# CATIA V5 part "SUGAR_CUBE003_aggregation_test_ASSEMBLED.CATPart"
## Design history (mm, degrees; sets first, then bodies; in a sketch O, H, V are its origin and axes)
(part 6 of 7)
Body52 "sugar_cube003_Aa006"
  Line326: type PtDir, RefPoint vertex of Line4, Direction edge [XY plane of AxisSystem1 | ZX plane of AxisSystem1], Start 0, End 4876.8 {= Body52.X1}
  Line327: type PtDir, RefPoint vertex of Line4, Direction edge [XY plane of AxisSystem1 | ZX plane of AxisSystem1], Start 0, End 4876.8 {= Body52.X2}
  Line328: type PtDir, RefPoint vertex of Line4, Direction edge [YZ plane of AxisSystem1 | XY plane of AxisSystem1], Start 0, End 3657.6 {= Body52.Y1}
  Line329: type PtDir, RefPoint vertex of Line4, Direction edge [YZ plane of AxisSystem1 | XY plane of AxisSystem1], Start 0, End 3352.8 {= Body52.Y2}
  Line330: type PtDir, RefPoint vertex of Line4, Direction edge [ZX plane of AxisSystem1 | YZ plane of AxisSystem1], Start 0, End 3048 {= Body52.Z1}
  Line331: type PtDir, RefPoint vertex of Line4, Direction edge [ZX plane of AxisSystem1 | YZ plane of AxisSystem1], Start 0, End 4572 {= Body52.Z2}
  Plane661: type Normal, Curve Line326, RefPoint vertex of Line326
  Plane662: type Normal, Curve Line327, RefPoint vertex of Line327
  Plane663: type Normal, Curve Line328, RefPoint vertex of Line328
  Plane664: type Normal, Curve Line329, RefPoint vertex of Line329
  Plane665: type Normal, Curve Line330, RefPoint vertex of Line330
  Plane666: type Normal, Curve Line331, RefPoint vertex of Line331
  Plane667: type 3Points, Element1 vertex of Line4, Element2 vertex of Line328, Element3 vertex of Line326
  Intersect1001: ToIntersect1 Plane663, ToIntersect2 Plane662
  Intersect1002: ToIntersect1 Plane661, ToIntersect2 Plane663
  Intersect1003: ToIntersect1 Plane661, ToIntersect2 Plane664
  Intersect1004: ToIntersect1 Plane664, ToIntersect2 Plane662
  MultiSel51
  LineCorner51: Elements ({intersect ToIntersect1 Plane667, ToIntersect2 Intersect1003}; {intersect ToIntersect1 Plane667, ToIntersect2 Intersect1004}; {intersect ToIntersect1 Plane667, ToIntersect2 Intersect1001}; {intersect ToIntersect1 Plane667, ToIntersect2 Intersect1002})
  Pad202: profile LineCorner51, up to Plane665, opposite side up to Plane666
  Plane668: type Offset, RefPlane Plane664, Offset 609.6 {= thickness}
  Plane669: type Offset, RefPlane Plane663, Offset 609.6 {= thickness}, reversed
  Plane670: type Offset, RefPlane Plane661, Offset 609.6 {= thickness}, reversed
  Plane671: type Offset, RefPlane Plane662, Offset 609.6 {= thickness}
  Plane672: type Offset, RefPlane Plane666, Offset 609.6 {= thickness}
  Plane673: type Offset, RefPlane Plane665, Offset 609.6 {= thickness}, reversed
  Intersect1005: ToIntersect1 Plane668, ToIntersect2 Plane661
  Intersect1006: ToIntersect1 Plane669, ToIntersect2 Plane661
  Intersect1007: ToIntersect1 Plane672, ToIntersect2 Plane661
  Intersect1008: ToIntersect1 Plane673, ToIntersect2 Plane661
  Trim601: Trimmed (Intersect1005; Intersect1008)
  Trim602: Trimmed (Trim601; Intersect1006)
  Trim603: Trimmed (Trim602; Intersect1007)
  Pocket206: profile Trim603, up to Plane671, deactivated
  Pad203: profile LineCorner51, up to Plane665, opposite side up to Plane666, deactivated
  Intersect1009: ToIntersect1 Plane669, ToIntersect2 Plane662
  Intersect1010: ToIntersect1 Plane662, ToIntersect2 Plane668
  Intersect1011: ToIntersect1 Plane672, ToIntersect2 Plane662
  Intersect1012: ToIntersect1 Plane673, ToIntersect2 Plane662
  Trim604: Trimmed (Intersect1012; Intersect1009)
  Trim605: Trimmed (Trim604; Intersect1011)
  Trim606: Trimmed (Trim605; Intersect1010)
  Pocket207: profile Trim606, up to Plane670, deactivated
  Intersect1013: ToIntersect1 Plane671, ToIntersect2 Plane664
  Intersect1014: ToIntersect1 Plane672, ToIntersect2 Plane664
  Intersect1015: ToIntersect1 Plane664, ToIntersect2 Plane670
  Intersect1016: ToIntersect1 Plane673, ToIntersect2 Plane664
  Trim607: Trimmed (Intersect1013; Intersect1016)
  Trim608: Trimmed (Trim607; Intersect1015)
  Trim609: Trimmed (Trim608; Intersect1014)
  Pad204: profile LineCorner51, up to Plane665, opposite side up to Plane666
  Pocket208: profile Trim609, up to Plane669
  Intersect1017: ToIntersect1 Plane670, ToIntersect2 Plane663
  Intersect1018: ToIntersect1 Plane672, ToIntersect2 Plane663
  Intersect1019: ToIntersect1 Plane671, ToIntersect2 Plane663
  Intersect1020: ToIntersect1 Plane673, ToIntersect2 Plane663
  Trim610: Trimmed (Intersect1017; Intersect1020)
  Trim611: Trimmed (Trim610; Intersect1019)
  Trim612: Trimmed (Trim611; Intersect1018)
  Pad205: profile LineCorner51, up to Plane665, opposite side up to Plane666, deactivated
  Pocket209: profile Trim612, up to Plane668, deactivated
Body53 "sugar_cube003_Ab006"
  Line332: type PtDir, RefPoint vertex of Line3, Direction edge [XY plane of AxisSystem1 | ZX plane of AxisSystem1], Start 0, End 3962.4 {= Body53.X1}
  Line333: type PtDir, RefPoint vertex of Line3, Direction edge [XY plane of AxisSystem1 | ZX plane of AxisSystem1], Start 0, End 3657.6 {= Body53.X2}
  Line334: type PtDir, RefPoint vertex of Line3, Direction edge [YZ plane of AxisSystem1 | XY plane of AxisSystem1], Start 0, End 4876.8 {= Body53.Y1}
  Line335: type PtDir, RefPoint vertex of Line3, Direction edge [YZ plane of AxisSystem1 | XY plane of AxisSystem1], Start 0, End 3962.4 {= Body53.Y2}
  Line336: type PtDir, RefPoint vertex of Line3, Direction edge [ZX plane of AxisSystem1 | YZ plane of AxisSystem1], Start 0, End 3352.8 {= Body53.Z1}
  Line337: type PtDir, RefPoint vertex of Line3, Direction edge [ZX plane of AxisSystem1 | YZ plane of AxisSystem1], Start 0, End 3657.6 {= Body53.Z2}
  Plane674: type Normal, Curve Line332, RefPoint vertex of Line332
  Plane675: type Normal, Curve Line333, RefPoint vertex of Line333
  Plane676: type Normal, Curve Line334, RefPoint vertex of Line334
  Plane677: type Normal, Curve Line335, RefPoint vertex of Line335
  Plane678: type Normal, Curve Line336, RefPoint vertex of Line336
  Plane679: type Normal, Curve Line337, RefPoint vertex of Line337
  Plane680: type 3Points, Element1 vertex of Line3, Element2 vertex of Line334, Element3 vertex of Line332
  Intersect1021: ToIntersect1 Plane676, ToIntersect2 Plane675
  Intersect1022: ToIntersect1 Plane674, ToIntersect2 Plane676
  Intersect1023: ToIntersect1 Plane674, ToIntersect2 Plane677
  Intersect1024: ToIntersect1 Plane677, ToIntersect2 Plane675
  MultiSel52
  LineCorner52: Elements ({intersect ToIntersect1 Plane680, ToIntersect2 Intersect1023}; {intersect ToIntersect1 Plane680, ToIntersect2 Intersect1024}; {intersect ToIntersect1 Plane680, ToIntersect2 Intersect1021}; {intersect ToIntersect1 Plane680, ToIntersect2 Intersect1022})
  Pad206: profile LineCorner52, up to Plane678, opposite side up to Plane679
  Plane681: type Offset, RefPlane Plane677, Offset 609.6 {= thickness}
  Plane682: type Offset, RefPlane Plane676, Offset 609.6 {= thickness}, reversed
  Plane683: type Offset, RefPlane Plane674, Offset 609.6 {= thickness}, reversed
  Plane684: type Offset, RefPlane Plane675, Offset 609.6 {= thickness}
  Plane685: type Offset, RefPlane Plane679, Offset 609.6 {= thickness}
  Plane686: type Offset, RefPlane Plane678, Offset 609.6 {= thickness}, reversed
  Intersect1025: ToIntersect1 Plane681, ToIntersect2 Plane674
  Intersect1026: ToIntersect1 Plane682, ToIntersect2 Plane674
  Intersect1027: ToIntersect1 Plane685, ToIntersect2 Plane674
  Intersect1028: ToIntersect1 Plane686, ToIntersect2 Plane674
  Trim613: Trimmed (Intersect1025; Intersect1028)
  Trim614: Trimmed (Trim613; Intersect1026)
  Trim615: Trimmed (Trim614; Intersect1027)
  Pocket210: profile Trim615, up to Plane684
  Pad207: profile LineCorner52, up to Plane678, opposite side up to Plane679, deactivated
  Intersect1029: ToIntersect1 Plane682, ToIntersect2 Plane675
  Intersect1030: ToIntersect1 Plane675, ToIntersect2 Plane681
  Intersect1031: ToIntersect1 Plane685, ToIntersect2 Plane675
  Intersect1032: ToIntersect1 Plane686, ToIntersect2 Plane675
  Trim616: Trimmed (Intersect1032; Intersect1029)
  Trim617: Trimmed (Trim616; Intersect1031)
  Trim618: Trimmed (Trim617; Intersect1030)
  Pocket211: profile Trim618, up to Plane683, deactivated
  Intersect1033: ToIntersect1 Plane684, ToIntersect2 Plane677
  Intersect1034: ToIntersect1 Plane685, ToIntersect2 Plane677
  Intersect1035: ToIntersect1 Plane677, ToIntersect2 Plane683
  Intersect1036: ToIntersect1 Plane686, ToIntersect2 Plane677
  Trim619: Trimmed (Intersect1033; Intersect1036)
  Trim620: Trimmed (Trim619; Intersect1035)
  Trim621: Trimmed (Trim620; Intersect1034)
  Pad208: profile LineCorner52, up to Plane678, opposite side up to Plane679, deactivated
  Pocket212: profile Trim621, up to Plane682, deactivated
  Intersect1037: ToIntersect1 Plane683, ToIntersect2 Plane676
  Intersect1038: ToIntersect1 Plane685, ToIntersect2 Plane676
  Intersect1039: ToIntersect1 Plane684, ToIntersect2 Plane676
  Intersect1040: ToIntersect1 Plane686, ToIntersect2 Plane676
  Trim622: Trimmed (Intersect1037; Intersect1040)
  Trim623: Trimmed (Trim622; Intersect1039)
  Trim624: Trimmed (Trim623; Intersect1038)
  Pad209: profile LineCorner52, up to Plane678, opposite side up to Plane679, deactivated
  Pocket213: profile Trim624, up to Plane681, deactivated
Body54 "sugar_cube003Ac006"
  Line338: type PtDir, RefPoint vertex of Line2, Direction edge [XY plane of AxisSystem1 | ZX plane of AxisSystem1], Start 0, End 4572 {= Body54.X1}
  Line339: type PtDir, RefPoint vertex of Line2, Direction edge [XY plane of AxisSystem1 | ZX plane of AxisSystem1], Start 0, End 5791.2 {= Body54.X2}
  Line340: type PtDir, RefPoint vertex of Line2, Direction edge [YZ plane of AxisSystem1 | XY plane of AxisSystem1], Start 0, End 3048 {= Body54.Y1}
  Line341: type PtDir, RefPoint vertex of Line2, Direction edge [YZ plane of AxisSystem1 | XY plane of AxisSystem1], Start 0, End 3657.6 {= Body54.Y2}
  Line342: type PtDir, RefPoint vertex of Line2, Direction edge [ZX plane of AxisSystem1 | YZ plane of AxisSystem1], Start 0, End 6096 {= Body54.Z1}
  Line343: type PtDir, RefPoint vertex of Line2, Direction edge [ZX plane of AxisSystem1 | YZ plane of AxisSystem1], Start 0, End 4572 {= Body54.Z2}
  Plane687: type Normal, Curve Line338, RefPoint vertex of Line338
  Plane688: type Normal, Curve Line339, RefPoint vertex of Line339
  Plane689: type Normal, Curve Line340, RefPoint vertex of Line340
  Plane690: type Normal, Curve Line341, RefPoint vertex of Line341
  Plane691: type Normal, Curve Line342, RefPoint vertex of Line342
  Plane692: type Normal, Curve Line343, RefPoint vertex of Line343
  Plane693: type 3Points, Element1 vertex of Line2, Element2 vertex of Line340, Element3 vertex of Line338
  Intersect1041: ToIntersect1 Plane689, ToIntersect2 Plane688
  Intersect1042: ToIntersect1 Plane687, ToIntersect2 Plane689
  Intersect1043: ToIntersect1 Plane687, ToIntersect2 Plane690
  Intersect1044: ToIntersect1 Plane690, ToIntersect2 Plane688
  MultiSel53
  LineCorner53: Elements ({intersect ToIntersect1 Plane693, ToIntersect2 Intersect1043}; {intersect ToIntersect1 Plane693, ToIntersect2 Intersect1044}; {intersect ToIntersect1 Plane693, ToIntersect2 Intersect1041}; {intersect ToIntersect1 Plane693, ToIntersect2 Intersect1042})
  Pad210: profile LineCorner53, up to Plane691, opposite side up to Plane692, deactivated
  Plane694: type Offset, RefPlane Plane690, Offset 609.6 {= thickness}
  Plane695: type Offset, RefPlane Plane689, Offset 609.6 {= thickness}, reversed
  Plane696: type Offset, RefPlane Plane687, Offset 609.6 {= thickness}, reversed
  Plane697: type Offset, RefPlane Plane688, Offset 609.6 {= thickness}
  Plane698: type Offset, RefPlane Plane692, Offset 609.6 {= thickness}
  Plane699: type Offset, RefPlane Plane691, Offset 609.6 {= thickness}, reversed
  Intersect1045: ToIntersect1 Plane694, ToIntersect2 Plane687
  Intersect1046: ToIntersect1 Plane695, ToIntersect2 Plane687
  Intersect1047: ToIntersect1 Plane698, ToIntersect2 Plane687
  Intersect1048: ToIntersect1 Plane699, ToIntersect2 Plane687
  Trim625: Trimmed (Intersect1045; Intersect1048)
  Trim626: Trimmed (Trim625; Intersect1046)
  Trim627: Trimmed (Trim626; Intersect1047)
  Pocket214: profile Trim627, up to Plane697, deactivated
  Pad211: profile LineCorner53, up to Plane691, opposite side up to Plane692
  Intersect1049: ToIntersect1 Plane695, ToIntersect2 Plane688
  Intersect1050: ToIntersect1 Plane688, ToIntersect2 Plane694
  Intersect1051: ToIntersect1 Plane698, ToIntersect2 Plane688
  Intersect1052: ToIntersect1 Plane699, ToIntersect2 Plane688
  Trim628: Trimmed (Intersect1052; Intersect1049)
  Trim629: Trimmed (Trim628; Intersect1051)
  Trim630: Trimmed (Trim629; Intersect1050)
  Pocket215: profile Trim630, up to Plane696
  Intersect1053: ToIntersect1 Plane697, ToIntersect2 Plane690
  Intersect1054: ToIntersect1 Plane698, ToIntersect2 Plane690
  Intersect1055: ToIntersect1 Plane690, ToIntersect2 Plane696
  Intersect1056: ToIntersect1 Plane699, ToIntersect2 Plane690
  Trim631: Trimmed (Intersect1053; Intersect1056)
  Trim632: Trimmed (Trim631; Intersect1055)
  Trim633: Trimmed (Trim632; Intersect1054)
  Pad212: profile LineCorner53, up to Plane691, opposite side up to Plane692, deactivated
  Pocket216: profile Trim633, up to Plane695, deactivated
  Intersect1057: ToIntersect1 Plane696, ToIntersect2 Plane689
  Intersect1058: ToIntersect1 Plane698, ToIntersect2 Plane689
  Intersect1059: ToIntersect1 Plane697, ToIntersect2 Plane689
  Intersect1060: ToIntersect1 Plane699, ToIntersect2 Plane689
  Trim634: Trimmed (Intersect1057; Intersect1060)
  Trim635: Trimmed (Trim634; Intersect1059)
  Trim636: Trimmed (Trim635; Intersect1058)
  Pad213: profile LineCorner53, up to Plane691, opposite side up to Plane692, deactivated
  Pocket217: profile Trim636, up to Plane694, deactivated
Body55 "sugar_cube003_Ad006"
  Line344: type PtDir, RefPoint vertex of Line1, Direction edge [XY plane of AxisSystem1 | ZX plane of AxisSystem1], Start 0, End 4267.2 {= Body55.X1}
  Line345: type PtDir, RefPoint vertex of Line1, Direction edge [XY plane of AxisSystem1 | ZX plane of AxisSystem1], Start 0, End 6096 {= Body55.X2}
  Line346: type PtDir, RefPoint vertex of Line1, Direction edge [YZ plane of AxisSystem1 | XY plane of AxisSystem1], Start 0, End 3352.8 {= Body55.Y1}
  Line347: type PtDir, RefPoint vertex of Line1, Direction edge [YZ plane of AxisSystem1 | XY plane of AxisSystem1], Start 0, End 4267.2 {= Body55.Y2}
  Line348: type PtDir, RefPoint vertex of Line1, Direction edge [ZX plane of AxisSystem1 | YZ plane of AxisSystem1], Start 0, End 3962.4 {= Body55.Z1}
  Line349: type PtDir, RefPoint vertex of Line1, Direction edge [ZX plane of AxisSystem1 | YZ plane of AxisSystem1], Start 0, End 3962.4 {= Body55.Z2}
  Plane700: type Normal, Curve Line344, RefPoint vertex of Line344
  Plane701: type Normal, Curve Line345, RefPoint vertex of Line345
  Plane702: type Normal, Curve Line346, RefPoint vertex of Line346
  Plane703: type Normal, Curve Line347, RefPoint vertex of Line347
  Plane704: type Normal, Curve Line348, RefPoint vertex of Line348
  Plane705: type Normal, Curve Line349, RefPoint vertex of Line349
  Plane706: type 3Points, Element1 vertex of Line1, Element2 vertex of Line346, Element3 vertex of Line344
  Intersect1061: ToIntersect1 Plane702, ToIntersect2 Plane701
  Intersect1062: ToIntersect1 Plane700, ToIntersect2 Plane702
  Intersect1063: ToIntersect1 Plane700, ToIntersect2 Plane703
  Intersect1064: ToIntersect1 Plane703, ToIntersect2 Plane701
  MultiSel54
  LineCorner54: Elements ({intersect ToIntersect1 Plane706, ToIntersect2 Intersect1063}; {intersect ToIntersect1 Plane706, ToIntersect2 Intersect1064}; {intersect ToIntersect1 Plane706, ToIntersect2 Intersect1061}; {intersect ToIntersect1 Plane706, ToIntersect2 Intersect1062})
  Pad214: profile LineCorner54, up to Plane704, opposite side up to Plane705, deactivated
  Plane707: type Offset, RefPlane Plane703, Offset 609.6 {= thickness}
  Plane708: type Offset, RefPlane Plane702, Offset 609.6 {= thickness}, reversed
  Plane709: type Offset, RefPlane Plane700, Offset 609.6 {= thickness}, reversed
  Plane710: type Offset, RefPlane Plane701, Offset 609.6 {= thickness}
  Plane711: type Offset, RefPlane Plane705, Offset 609.6 {= thickness}
  Plane712: type Offset, RefPlane Plane704, Offset 609.6 {= thickness}, reversed
  Intersect1065: ToIntersect1 Plane707, ToIntersect2 Plane700
  Intersect1066: ToIntersect1 Plane708, ToIntersect2 Plane700
  Intersect1067: ToIntersect1 Plane711, ToIntersect2 Plane700
  Intersect1068: ToIntersect1 Plane712, ToIntersect2 Plane700
  Trim637: Trimmed (Intersect1065; Intersect1068)
  Trim638: Trimmed (Trim637; Intersect1066)
  Trim639: Trimmed (Trim638; Intersect1067)
  Pocket218: profile Trim639, up to Plane710, deactivated
  Pad215: profile LineCorner54, up to Plane704, opposite side up to Plane705
  Intersect1069: ToIntersect1 Plane708, ToIntersect2 Plane701
  Intersect1070: ToIntersect1 Plane701, ToIntersect2 Plane707
  Intersect1071: ToIntersect1 Plane711, ToIntersect2 Plane701
  Intersect1072: ToIntersect1 Plane712, ToIntersect2 Plane701
  Trim640: Trimmed (Intersect1072; Intersect1069)
  Trim641: Trimmed (Trim640; Intersect1071)
  Trim642: Trimmed (Trim641; Intersect1070)
  Pocket219: profile Trim642, up to Plane709
  Intersect1073: ToIntersect1 Plane710, ToIntersect2 Plane703
  Intersect1074: ToIntersect1 Plane711, ToIntersect2 Plane703
  Intersect1075: ToIntersect1 Plane703, ToIntersect2 Plane709
  Intersect1076: ToIntersect1 Plane712, ToIntersect2 Plane703
  Trim643: Trimmed (Intersect1073; Intersect1076)
  Trim644: Trimmed (Trim643; Intersect1075)
  Trim645: Trimmed (Trim644; Intersect1074)
  Pad216: profile LineCorner54, up to Plane704, opposite side up to Plane705, deactivated
  Pocket220: profile Trim645, up to Plane708, deactivated
  Intersect1077: ToIntersect1 Plane709, ToIntersect2 Plane702
  Intersect1078: ToIntersect1 Plane711, ToIntersect2 Plane702
  Intersect1079: ToIntersect1 Plane710, ToIntersect2 Plane702
  Intersect1080: ToIntersect1 Plane712, ToIntersect2 Plane702
  Trim646: Trimmed (Intersect1077; Intersect1080)
  Trim647: Trimmed (Trim646; Intersect1079)
  Trim648: Trimmed (Trim647; Intersect1078)
  Pad217: profile LineCorner54, up to Plane704, opposite side up to Plane705, deactivated
  Pocket221: profile Trim648, up to Plane707, deactivated
Body56 "_Ae006"
  Line350: type PtDir, RefPoint vertex of Line25, Direction edge [XY plane of AxisSystem1 | ZX plane of AxisSystem1], Start 0, End 4572 {= Body56.X1}
  Line351: type PtDir, RefPoint vertex of Line25, Direction edge [XY plane of AxisSystem1 | ZX plane of AxisSystem1], Start 0, End 5486.4 {= Body56.X2}
  Line352: type PtDir, RefPoint vertex of Line25, Direction edge [YZ plane of AxisSystem1 | XY plane of AxisSystem1], Start 0, End 3048 {= Body56.Y1}
  Line353: type PtDir, RefPoint vertex of Line25, Direction edge [YZ plane of AxisSystem1 | XY plane of AxisSystem1], Start 0, End 4267.2 {= Body56.Y2}
  Line354: type PtDir, RefPoint vertex of Line25, Direction edge [ZX plane of AxisSystem1 | YZ plane of AxisSystem1], Start 0, End 5791.2 {= Body56.Z1}
  Line355: type PtDir, RefPoint vertex of Line25, Direction edge [ZX plane of AxisSystem1 | YZ plane of AxisSystem1], Start 0, End 3048 {= Body56.Z2}
  Plane713: type Normal, Curve Line350, RefPoint vertex of Line350
  Plane714: type Normal, Curve Line351, RefPoint vertex of Line351
  Plane715: type Normal, Curve Line352, RefPoint vertex of Line352
  Plane716: type Normal, Curve Line353, RefPoint vertex of Line353
  Plane717: type Normal, Curve Line354, RefPoint vertex of Line354
  Plane718: type Normal, Curve Line355, RefPoint vertex of Line355
  Plane719: type 3Points, Element1 vertex of Line25, Element2 vertex of Line352, Element3 vertex of Line350
  Intersect1081: ToIntersect1 Plane715, ToIntersect2 Plane714
  Intersect1082: ToIntersect1 Plane713, ToIntersect2 Plane715
  Intersect1083: ToIntersect1 Plane713, ToIntersect2 Plane716
  Intersect1084: ToIntersect1 Plane716, ToIntersect2 Plane714
  MultiSel55
  LineCorner55: Elements ({intersect ToIntersect1 Plane719, ToIntersect2 Intersect1083}; {intersect ToIntersect1 Plane719, ToIntersect2 Intersect1084}; {intersect ToIntersect1 Plane719, ToIntersect2 Intersect1081}; {intersect ToIntersect1 Plane719, ToIntersect2 Intersect1082})
  Pad218: profile LineCorner55, up to Plane717, opposite side up to Plane718, deactivated
  Plane720: type Offset, RefPlane Plane716, Offset 609.6 {= thickness}
  Plane721: type Offset, RefPlane Plane715, Offset 609.6 {= thickness}, reversed
  Plane722: type Offset, RefPlane Plane713, Offset 609.6 {= thickness}, reversed
  Plane723: type Offset, RefPlane Plane714, Offset 609.6 {= thickness}
  Plane724: type Offset, RefPlane Plane718, Offset 609.6 {= thickness}
  Plane725: type Offset, RefPlane Plane717, Offset 609.6 {= thickness}, reversed
  Intersect1085: ToIntersect1 Plane720, ToIntersect2 Plane713
  Intersect1086: ToIntersect1 Plane721, ToIntersect2 Plane713
  Intersect1087: ToIntersect1 Plane724, ToIntersect2 Plane713
  Intersect1088: ToIntersect1 Plane725, ToIntersect2 Plane713
  Trim649: Trimmed (Intersect1085; Intersect1088)
  Trim650: Trimmed (Trim649; Intersect1086)
  Trim651: Trimmed (Trim650; Intersect1087)
  Pocket222: profile Trim651, up to Plane723, deactivated
  Pad219: profile LineCorner55, up to Plane717, opposite side up to Plane718, deactivated
  Intersect1089: ToIntersect1 Plane721, ToIntersect2 Plane714
  Intersect1090: ToIntersect1 Plane714, ToIntersect2 Plane720
  Intersect1091: ToIntersect1 Plane724, ToIntersect2 Plane714
  Intersect1092: ToIntersect1 Plane725, ToIntersect2 Plane714
  Trim652: Trimmed (Intersect1092; Intersect1089)
  Trim653: Trimmed (Trim652; Intersect1091)
  Trim654: Trimmed (Trim653; Intersect1090)
  Pocket223: profile Trim654, up to Plane722, deactivated
  Intersect1093: ToIntersect1 Plane723, ToIntersect2 Plane716
  Intersect1094: ToIntersect1 Plane724, ToIntersect2 Plane716
  Intersect1095: ToIntersect1 Plane716, ToIntersect2 Plane722
  Intersect1096: ToIntersect1 Plane725, ToIntersect2 Plane716
  Trim655: Trimmed (Intersect1093; Intersect1096)
  Trim656: Trimmed (Trim655; Intersect1095)
  Trim657: Trimmed (Trim656; Intersect1094)
  Pad220: profile LineCorner55, up to Plane717, opposite side up to Plane718, deactivated
  Pocket224: profile Trim657, up to Plane721, deactivated
  Intersect1097: ToIntersect1 Plane722, ToIntersect2 Plane715
  Intersect1098: ToIntersect1 Plane724, ToIntersect2 Plane715
  Intersect1099: ToIntersect1 Plane723, ToIntersect2 Plane715
  Intersect1100: ToIntersect1 Plane725, ToIntersect2 Plane715
  Trim658: Trimmed (Intersect1097; Intersect1100)
  Trim659: Trimmed (Trim658; Intersect1099)
  Trim660: Trimmed (Trim659; Intersect1098)
  Pad221: profile LineCorner55, up to Plane717, opposite side up to Plane718, deactivated
  Pocket225: profile Trim660, up to Plane720, deactivated
Body57 "sugar_cube003Ba001"
  Line356: type PtDir, RefPoint vertex of Line9, Direction edge [XY plane of AxisSystem1 | ZX plane of AxisSystem1], Start 0, End 3657.6 {= Body57.X1}
  Line357: type PtDir, RefPoint vertex of Line9, Direction edge [XY plane of AxisSystem1 | ZX plane of AxisSystem1], Start 0, End 4876.8 {= Body57.X2}
  Line358: type PtDir, RefPoint vertex of Line9, Direction edge [YZ plane of AxisSystem1 | XY plane of AxisSystem1], Start 0, End 4267.2 {= Body57.Y1}
  Line359: type PtDir, RefPoint vertex of Line9, Direction edge [YZ plane of AxisSystem1 | XY plane of AxisSystem1], Start 0, End 5181.6 {= Body57.Y2}
  Line360: type PtDir, RefPoint vertex of Line9, Direction edge [ZX plane of AxisSystem1 | YZ plane of AxisSystem1], Start 0, End 5486.4 {= Body57.Z1}
  Line361: type PtDir, RefPoint vertex of Line9, Direction edge [ZX plane of AxisSystem1 | YZ plane of AxisSystem1], Start 0, End 3962.4 {= Body57.Z2}
  Plane726: type Normal, Curve Line356, RefPoint vertex of Line356
  Plane727: type Normal, Curve Line357, RefPoint vertex of Line357
  Plane728: type Normal, Curve Line358, RefPoint vertex of Line358
  Plane729: type Normal, Curve Line359, RefPoint vertex of Line359
  Plane730: type Normal, Curve Line360, RefPoint vertex of Line360
  Plane731: type Normal, Curve Line361, RefPoint vertex of Line361
  Plane732: type 3Points, Element1 vertex of Line9, Element2 vertex of Line358, Element3 vertex of Line356
  Intersect1101: ToIntersect1 Plane728, ToIntersect2 Plane727
  Intersect1102: ToIntersect1 Plane726, ToIntersect2 Plane728
  Intersect1103: ToIntersect1 Plane726, ToIntersect2 Plane729
  Intersect1104: ToIntersect1 Plane729, ToIntersect2 Plane727
  MultiSel56
  LineCorner56: Elements ({intersect ToIntersect1 Plane732, ToIntersect2 Intersect1103}; {intersect ToIntersect1 Plane732, ToIntersect2 Intersect1104}; {intersect ToIntersect1 Plane732, ToIntersect2 Intersect1101}; {intersect ToIntersect1 Plane732, ToIntersect2 Intersect1102})
  Pad222: profile LineCorner56, up to Plane730, opposite side up to Plane731
  Plane733: type Offset, RefPlane Plane729, Offset 609.6 {= thickness}
  Plane734: type Offset, RefPlane Plane728, Offset 609.6 {= thickness}, reversed
  Plane735: type Offset, RefPlane Plane726, Offset 609.6 {= thickness}, reversed
  Plane736: type Offset, RefPlane Plane727, Offset 609.6 {= thickness}
  Plane737: type Offset, RefPlane Plane731, Offset 609.6 {= thickness}
  Plane738: type Offset, RefPlane Plane730, Offset 609.6 {= thickness}, reversed
  Intersect1105: ToIntersect1 Plane733, ToIntersect2 Plane726
  Intersect1106: ToIntersect1 Plane734, ToIntersect2 Plane726
  Intersect1107: ToIntersect1 Plane737, ToIntersect2 Plane726
  Intersect1108: ToIntersect1 Plane738, ToIntersect2 Plane726
  Trim661: Trimmed (Intersect1105; Intersect1108)
  Trim662: Trimmed (Trim661; Intersect1106)
  Trim663: Trimmed (Trim662; Intersect1107)
  Pocket226: profile Trim663, up to Plane736, deactivated
  Pad223: profile LineCorner56, up to Plane730, opposite side up to Plane731, deactivated
  Intersect1109: ToIntersect1 Plane734, ToIntersect2 Plane727
  Intersect1110: ToIntersect1 Plane727, ToIntersect2 Plane733
  Intersect1111: ToIntersect1 Plane737, ToIntersect2 Plane727
  Intersect1112: ToIntersect1 Plane738, ToIntersect2 Plane727
  Trim664: Trimmed (Intersect1112; Intersect1109)
  Trim665: Trimmed (Trim664; Intersect1111)
  Trim666: Trimmed (Trim665; Intersect1110)
  Pocket227: profile Trim666, up to Plane735, deactivated
  Intersect1113: ToIntersect1 Plane736, ToIntersect2 Plane729
  Intersect1114: ToIntersect1 Plane737, ToIntersect2 Plane729
  Intersect1115: ToIntersect1 Plane729, ToIntersect2 Plane735
  Intersect1116: ToIntersect1 Plane738, ToIntersect2 Plane729
  Trim667: Trimmed (Intersect1113; Intersect1116)
  Trim668: Trimmed (Trim667; Intersect1115)
  Trim669: Trimmed (Trim668; Intersect1114)
  Pad224: profile LineCorner56, up to Plane730, opposite side up to Plane731, deactivated
  Pocket228: profile Trim669, up to Plane734, deactivated
  Intersect1117: ToIntersect1 Plane735, ToIntersect2 Plane728
  Intersect1118: ToIntersect1 Plane737, ToIntersect2 Plane728
  Intersect1119: ToIntersect1 Plane736, ToIntersect2 Plane728
  Intersect1120: ToIntersect1 Plane738, ToIntersect2 Plane728
  Trim670: Trimmed (Intersect1117; Intersect1120)
  Trim671: Trimmed (Trim670; Intersect1119)
  Trim672: Trimmed (Trim671; Intersect1118)
  Pad225: profile LineCorner56, up to Plane730, opposite side up to Plane731
  Pocket229: profile Trim672, up to Plane733
Body58 "sugar_cube003Bb001"
  Line362: type PtDir, RefPoint vertex of Line8, Direction edge [XY plane of AxisSystem1 | ZX plane of AxisSystem1], Start 0, End 4876.8 {= Body58.X1}
  Line363: type PtDir, RefPoint vertex of Line8, Direction edge [XY plane of AxisSystem1 | ZX plane of AxisSystem1], Start 0, End 6096 {= Body58.X2}
  Line364: type PtDir, RefPoint vertex of Line8, Direction edge [YZ plane of AxisSystem1 | XY plane of AxisSystem1], Start 0, End 3657.6 {= Body58.Y1}
  Line365: type PtDir, RefPoint vertex of Line8, Direction edge [YZ plane of AxisSystem1 | XY plane of AxisSystem1], Start 0, End 3962.4 {= Body58.Y2}
  Line366: type PtDir, RefPoint vertex of Line8, Direction edge [ZX plane of AxisSystem1 | YZ plane of AxisSystem1], Start 0, End 5791.2 {= Body58.Z1}
  Line367: type PtDir, RefPoint vertex of Line8, Direction edge [ZX plane of AxisSystem1 | YZ plane of AxisSystem1], Start 0, End 5181.6 {= Body58.Z2}
  Plane739: type Normal, Curve Line362, RefPoint vertex of Line362
  Plane740: type Normal, Curve Line363, RefPoint vertex of Line363
  Plane741: type Normal, Curve Line364, RefPoint vertex of Line364
  Plane742: type Normal, Curve Line365, RefPoint vertex of Line365
  Plane743: type Normal, Curve Line366, RefPoint vertex of Line366
  Plane744: type Normal, Curve Line367, RefPoint vertex of Line367
  Plane745: type 3Points, Element1 vertex of Line8, Element2 vertex of Line364, Element3 vertex of Line362
  Intersect1121: ToIntersect1 Plane741, ToIntersect2 Plane740
  Intersect1122: ToIntersect1 Plane739, ToIntersect2 Plane741
  Intersect1123: ToIntersect1 Plane739, ToIntersect2 Plane742
  Intersect1124: ToIntersect1 Plane742, ToIntersect2 Plane740
  MultiSel57
  LineCorner57: Elements ({intersect ToIntersect1 Plane745, ToIntersect2 Intersect1123}; {intersect ToIntersect1 Plane745, ToIntersect2 Intersect1124}; {intersect ToIntersect1 Plane745, ToIntersect2 Intersect1121}; {intersect ToIntersect1 Plane745, ToIntersect2 Intersect1122})
  Pad226: profile LineCorner57, up to Plane743, opposite side up to Plane744, deactivated
  Plane746: type Offset, RefPlane Plane742, Offset 609.6 {= thickness}
  Plane747: type Offset, RefPlane Plane741, Offset 609.6 {= thickness}, reversed
  Plane748: type Offset, RefPlane Plane739, Offset 609.6 {= thickness}, reversed
  Plane749: type Offset, RefPlane Plane740, Offset 609.6 {= thickness}
  Plane750: type Offset, RefPlane Plane744, Offset 609.6 {= thickness}
  Plane751: type Offset, RefPlane Plane743, Offset 609.6 {= thickness}, reversed
  Intersect1125: ToIntersect1 Plane746, ToIntersect2 Plane739
  Intersect1126: ToIntersect1 Plane747, ToIntersect2 Plane739
  Intersect1127: ToIntersect1 Plane750, ToIntersect2 Plane739
  Intersect1128: ToIntersect1 Plane751, ToIntersect2 Plane739
  Trim673: Trimmed (Intersect1125; Intersect1128)
  Trim674: Trimmed (Trim673; Intersect1126)
  Trim675: Trimmed (Trim674; Intersect1127)
  Pocket230: profile Trim675, up to Plane749, deactivated
  Pad227: profile LineCorner57, up to Plane743, opposite side up to Plane744, deactivated
  Intersect1129: ToIntersect1 Plane747, ToIntersect2 Plane740
  Intersect1130: ToIntersect1 Plane740, ToIntersect2 Plane746
  Intersect1131: ToIntersect1 Plane750, ToIntersect2 Plane740
  Intersect1132: ToIntersect1 Plane751, ToIntersect2 Plane740
  Trim676: Trimmed (Intersect1132; Intersect1129)
  Trim677: Trimmed (Trim676; Intersect1131)
  Trim678: Trimmed (Trim677; Intersect1130)
  Pocket231: profile Trim678, up to Plane748, deactivated
  Intersect1133: ToIntersect1 Plane749, ToIntersect2 Plane742
  Intersect1134: ToIntersect1 Plane750, ToIntersect2 Plane742
  Intersect1135: ToIntersect1 Plane742, ToIntersect2 Plane748
  Intersect1136: ToIntersect1 Plane751, ToIntersect2 Plane742
  Trim679: Trimmed (Intersect1133; Intersect1136)
  Trim680: Trimmed (Trim679; Intersect1135)
  Trim681: Trimmed (Trim680; Intersect1134)
  Pad228: profile LineCorner57, up to Plane743, opposite side up to Plane744
  Pocket232: profile Trim681, up to Plane747
  Intersect1137: ToIntersect1 Plane748, ToIntersect2 Plane741
  Intersect1138: ToIntersect1 Plane750, ToIntersect2 Plane741
  Intersect1139: ToIntersect1 Plane749, ToIntersect2 Plane741
  Intersect1140: ToIntersect1 Plane751, ToIntersect2 Plane741
  Trim682: Trimmed (Intersect1137; Intersect1140)
  Trim683: Trimmed (Trim682; Intersect1139)
  Trim684: Trimmed (Trim683; Intersect1138)
  Pad229: profile LineCorner57, up to Plane743, opposite side up to Plane744, deactivated
  Pocket233: profile Trim684, up to Plane746, deactivated
Body59 "sugar_cube003Bc001"
  Line368: type PtDir, RefPoint vertex of Line7, Direction edge [XY plane of AxisSystem1 | ZX plane of AxisSystem1], Start 0, End 4267.2 {= Body59.X1}
  Line369: type PtDir, RefPoint vertex of Line7, Direction edge [XY plane of AxisSystem1 | ZX plane of AxisSystem1], Start 0, End 4572 {= Body59.X2}
  Line370: type PtDir, RefPoint vertex of Line7, Direction edge [YZ plane of AxisSystem1 | XY plane of AxisSystem1], Start 0, End 3962.4 {= Body59.Y1}
  Line371: type PtDir, RefPoint vertex of Line7, Direction edge [YZ plane of AxisSystem1 | XY plane of AxisSystem1], Start 0, End 3352.8 {= Body59.Y2}
  Line372: type PtDir, RefPoint vertex of Line7, Direction edge [ZX plane of AxisSystem1 | YZ plane of AxisSystem1], Start 0, End 3962.4 {= Body59.Z1}
  Line373: type PtDir, RefPoint vertex of Line7, Direction edge [ZX plane of AxisSystem1 | YZ plane of AxisSystem1], Start 0, End 5486.4 {= Body59.Z2}
  Plane752: type Normal, Curve Line368, RefPoint vertex of Line368
  Plane753: type Normal, Curve Line369, RefPoint vertex of Line369
  Plane754: type Normal, Curve Line370, RefPoint vertex of Line370
  Plane755: type Normal, Curve Line371, RefPoint vertex of Line371
  Plane756: type Normal, Curve Line372, RefPoint vertex of Line372
  Plane757: type Normal, Curve Line373, RefPoint vertex of Line373
  Plane758: type 3Points, Element1 vertex of Line7, Element2 vertex of Line370, Element3 vertex of Line368
  Intersect1141: ToIntersect1 Plane754, ToIntersect2 Plane753
  Intersect1142: ToIntersect1 Plane752, ToIntersect2 Plane754
  Intersect1143: ToIntersect1 Plane752, ToIntersect2 Plane755
  Intersect1144: ToIntersect1 Plane755, ToIntersect2 Plane753
  MultiSel58
  LineCorner58: Elements ({intersect ToIntersect1 Plane758, ToIntersect2 Intersect1143}; {intersect ToIntersect1 Plane758, ToIntersect2 Intersect1144}; {intersect ToIntersect1 Plane758, ToIntersect2 Intersect1141}; {intersect ToIntersect1 Plane758, ToIntersect2 Intersect1142})
  Pad230: profile LineCorner58, up to Plane756, opposite side up to Plane757, deactivated
  Plane759: type Offset, RefPlane Plane755, Offset 609.6 {= thickness}
  Plane760: type Offset, RefPlane Plane754, Offset 609.6 {= thickness}, reversed
  Plane761: type Offset, RefPlane Plane752, Offset 609.6 {= thickness}, reversed
  Plane762: type Offset, RefPlane Plane753, Offset 609.6 {= thickness}
  Plane763: type Offset, RefPlane Plane757, Offset 609.6 {= thickness}
  Plane764: type Offset, RefPlane Plane756, Offset 609.6 {= thickness}, reversed
  Intersect1145: ToIntersect1 Plane759, ToIntersect2 Plane752
  Intersect1146: ToIntersect1 Plane760, ToIntersect2 Plane752
  Intersect1147: ToIntersect1 Plane763, ToIntersect2 Plane752
  Intersect1148: ToIntersect1 Plane764, ToIntersect2 Plane752
  Trim685: Trimmed (Intersect1145; Intersect1148)
  Trim686: Trimmed (Trim685; Intersect1146)
  Trim687: Trimmed (Trim686; Intersect1147)
  Pocket234: profile Trim687, up to Plane762, deactivated
  Pad231: profile LineCorner58, up to Plane756, opposite side up to Plane757
  Intersect1149: ToIntersect1 Plane760, ToIntersect2 Plane753
  Intersect1150: ToIntersect1 Plane753, ToIntersect2 Plane759
  Intersect1151: ToIntersect1 Plane763, ToIntersect2 Plane753
  Intersect1152: ToIntersect1 Plane764, ToIntersect2 Plane753
  Trim688: Trimmed (Intersect1152; Intersect1149)
  Trim689: Trimmed (Trim688; Intersect1151)
  Trim690: Trimmed (Trim689; Intersect1150)
  Pocket235: profile Trim690, up to Plane761
  Intersect1153: ToIntersect1 Plane762, ToIntersect2 Plane755
  Intersect1154: ToIntersect1 Plane763, ToIntersect2 Plane755
  Intersect1155: ToIntersect1 Plane755, ToIntersect2 Plane761
  Intersect1156: ToIntersect1 Plane764, ToIntersect2 Plane755
  Trim691: Trimmed (Intersect1153; Intersect1156)
  Trim692: Trimmed (Trim691; Intersect1155)
  Trim693: Trimmed (Trim692; Intersect1154)
  Pad232: profile LineCorner58, up to Plane756, opposite side up to Plane757, deactivated
  Pocket236: profile Trim693, up to Plane760, deactivated
  Intersect1157: ToIntersect1 Plane761, ToIntersect2 Plane754
  Intersect1158: ToIntersect1 Plane763, ToIntersect2 Plane754
  Intersect1159: ToIntersect1 Plane762, ToIntersect2 Plane754
  Intersect1160: ToIntersect1 Plane764, ToIntersect2 Plane754
  Trim694: Trimmed (Intersect1157; Intersect1160)
  Trim695: Trimmed (Trim694; Intersect1159)
  Trim696: Trimmed (Trim695; Intersect1158)
  Pad233: profile LineCorner58, up to Plane756, opposite side up to Plane757, deactivated
  Pocket237: profile Trim696, up to Plane759, deactivated
Body60 "sugar_cube003Bd001"
  Line374: type PtDir, RefPoint vertex of Line6, Direction edge [XY plane of AxisSystem1 | ZX plane of AxisSystem1], Start 0, End 6096 {= Body60.X1}
  Line375: type PtDir, RefPoint vertex of Line6, Direction edge [XY plane of AxisSystem1 | ZX plane of AxisSystem1], Start 0, End 5486.4 {= Body60.X2}
  Line376: type PtDir, RefPoint vertex of Line6, Direction edge [YZ plane of AxisSystem1 | XY plane of AxisSystem1], Start 0, End 3657.6 {= Body60.Y1}
  Line377: type PtDir, RefPoint vertex of Line6, Direction edge [YZ plane of AxisSystem1 | XY plane of AxisSystem1], Start 0, End 5791.2 {= Body60.Y2}
  Line378: type PtDir, RefPoint vertex of Line6, Direction edge [ZX plane of AxisSystem1 | YZ plane of AxisSystem1], Start 0, End 3962.4 {= Body60.Z1}
  Line379: type PtDir, RefPoint vertex of Line6, Direction edge [ZX plane of AxisSystem1 | YZ plane of AxisSystem1], Start 0, End 3962.4 {= Body60.Z2}
  Plane765: type Normal, Curve Line374, RefPoint vertex of Line374
  Plane766: type Normal, Curve Line375, RefPoint vertex of Line375
  Plane767: type Normal, Curve Line376, RefPoint vertex of Line376
  Plane768: type Normal, Curve Line377, RefPoint vertex of Line377
  Plane769: type Normal, Curve Line378, RefPoint vertex of Line378
  Plane770: type Normal, Curve Line379, RefPoint vertex of Line379
  Plane771: type 3Points, Element1 vertex of Line6, Element2 vertex of Line376, Element3 vertex of Line374
  Intersect1161: ToIntersect1 Plane767, ToIntersect2 Plane766
  Intersect1162: ToIntersect1 Plane765, ToIntersect2 Plane767
  Intersect1163: ToIntersect1 Plane765, ToIntersect2 Plane768
  Intersect1164: ToIntersect1 Plane768, ToIntersect2 Plane766
  MultiSel59
  LineCorner59: Elements ({intersect ToIntersect1 Plane771, ToIntersect2 Intersect1163}; {intersect ToIntersect1 Plane771, ToIntersect2 Intersect1164}; {intersect ToIntersect1 Plane771, ToIntersect2 Intersect1161}; {intersect ToIntersect1 Plane771, ToIntersect2 Intersect1162})
  Pad234: profile LineCorner59, up to Plane769, opposite side up to Plane770
  Plane772: type Offset, RefPlane Plane768, Offset 609.6 {= thickness}
  Plane773: type Offset, RefPlane Plane767, Offset 609.6 {= thickness}, reversed
  Plane774: type Offset, RefPlane Plane765, Offset 609.6 {= thickness}, reversed
  Plane775: type Offset, RefPlane Plane766, Offset 609.6 {= thickness}
  Plane776: type Offset, RefPlane Plane770, Offset 609.6 {= thickness}
  Plane777: type Offset, RefPlane Plane769, Offset 609.6 {= thickness}, reversed
  Intersect1165: ToIntersect1 Plane772, ToIntersect2 Plane765
  Intersect1166: ToIntersect1 Plane773, ToIntersect2 Plane765
  Intersect1167: ToIntersect1 Plane776, ToIntersect2 Plane765
  Intersect1168: ToIntersect1 Plane777, ToIntersect2 Plane765
  Trim697: Trimmed (Intersect1165; Intersect1168)
  Trim698: Trimmed (Trim697; Intersect1166)
  Trim699: Trimmed (Trim698; Intersect1167)
  Pocket238: profile Trim699, up to Plane775, deactivated
  Pad235: profile LineCorner59, up to Plane769, opposite side up to Plane770, deactivated
  Intersect1169: ToIntersect1 Plane773, ToIntersect2 Plane766
  Intersect1170: ToIntersect1 Plane766, ToIntersect2 Plane772
  Intersect1171: ToIntersect1 Plane776, ToIntersect2 Plane766
  Intersect1172: ToIntersect1 Plane777, ToIntersect2 Plane766
  Trim700: Trimmed (Intersect1172; Intersect1169)
  Trim701: Trimmed (Trim700; Intersect1171)
  Trim702: Trimmed (Trim701; Intersect1170)
  Pocket239: profile Trim702, up to Plane774, deactivated
  Intersect1173: ToIntersect1 Plane775, ToIntersect2 Plane768
  Intersect1174: ToIntersect1 Plane776, ToIntersect2 Plane768
  Intersect1175: ToIntersect1 Plane768, ToIntersect2 Plane774
  Intersect1176: ToIntersect1 Plane777, ToIntersect2 Plane768
  Trim703: Trimmed (Intersect1173; Intersect1176)
  Trim704: Trimmed (Trim703; Intersect1175)
  Trim705: Trimmed (Trim704; Intersect1174)
  Pad236: profile LineCorner59, up to Plane769, opposite side up to Plane770, deactivated
  Pocket240: profile Trim705, up to Plane773, deactivated
  Intersect1177: ToIntersect1 Plane774, ToIntersect2 Plane767
  Intersect1178: ToIntersect1 Plane776, ToIntersect2 Plane767
  Intersect1179: ToIntersect1 Plane775, ToIntersect2 Plane767
  Intersect1180: ToIntersect1 Plane777, ToIntersect2 Plane767
  Trim706: Trimmed (Intersect1177; Intersect1180)
  Trim707: Trimmed (Trim706; Intersect1179)
  Trim708: Trimmed (Trim707; Intersect1178)
  Pad237: profile LineCorner59, up to Plane769, opposite side up to Plane770
  Pocket241: profile Trim708, up to Plane772
Body61 "sugar_cube003Be001"
  Line380: type PtDir, RefPoint vertex of Line5, Direction edge [XY plane of AxisSystem1 | ZX plane of AxisSystem1], Start 0, End 3048 {= Body61.X1}
  Line381: type PtDir, RefPoint vertex of Line5, Direction edge [XY plane of AxisSystem1 | ZX plane of AxisSystem1], Start 0, End 3657.6 {= Body61.X2}
  Line382: type PtDir, RefPoint vertex of Line5, Direction edge [YZ plane of AxisSystem1 | XY plane of AxisSystem1], Start 0, End 4876.8 {= Body61.Y1}
  Line383: type PtDir, RefPoint vertex of Line5, Direction edge [YZ plane of AxisSystem1 | XY plane of AxisSystem1], Start 0, End 6096 {= Body61.Y2}
  Line384: type PtDir, RefPoint vertex of Line5, Direction edge [ZX plane of AxisSystem1 | YZ plane of AxisSystem1], Start 0, End 4267.2 {= Body61.Z1}
  Line385: type PtDir, RefPoint vertex of Line5, Direction edge [ZX plane of AxisSystem1 | YZ plane of AxisSystem1], Start 0, End 3657.6 {= Body61.Z2}
  Plane778: type Normal, Curve Line380, RefPoint vertex of Line380
  Plane779: type Normal, Curve Line381, RefPoint vertex of Line381
  Plane780: type Normal, Curve Line382, RefPoint vertex of Line382
  Plane781: type Normal, Curve Line383, RefPoint vertex of Line383
  Plane782: type Normal, Curve Line384, RefPoint vertex of Line384
  Plane783: type Normal, Curve Line385, RefPoint vertex of Line385
  Plane784: type 3Points, Element1 vertex of Line5, Element2 vertex of Line382, Element3 vertex of Line380
  Intersect1181: ToIntersect1 Plane780, ToIntersect2 Plane779
  Intersect1182: ToIntersect1 Plane778, ToIntersect2 Plane780
  Intersect1183: ToIntersect1 Plane778, ToIntersect2 Plane781
  Intersect1184: ToIntersect1 Plane781, ToIntersect2 Plane779
  MultiSel60
  LineCorner60: Elements ({intersect ToIntersect1 Plane784, ToIntersect2 Intersect1183}; {intersect ToIntersect1 Plane784, ToIntersect2 Intersect1184}; {intersect ToIntersect1 Plane784, ToIntersect2 Intersect1181}; {intersect ToIntersect1 Plane784, ToIntersect2 Intersect1182})
  Pad238: profile LineCorner60, up to Plane782, opposite side up to Plane783
  Plane785: type Offset, RefPlane Plane781, Offset 609.6 {= thickness}
  Plane786: type Offset, RefPlane Plane780, Offset 609.6 {= thickness}, reversed
  Plane787: type Offset, RefPlane Plane778, Offset 609.6 {= thickness}, reversed
  Plane788: type Offset, RefPlane Plane779, Offset 609.6 {= thickness}
  Plane789: type Offset, RefPlane Plane783, Offset 609.6 {= thickness}
  Plane790: type Offset, RefPlane Plane782, Offset 609.6 {= thickness}, reversed
  Intersect1185: ToIntersect1 Plane785, ToIntersect2 Plane778
  Intersect1186: ToIntersect1 Plane786, ToIntersect2 Plane778
  Intersect1187: ToIntersect1 Plane789, ToIntersect2 Plane778
  Intersect1188: ToIntersect1 Plane790, ToIntersect2 Plane778
  Trim709: Trimmed (Intersect1185; Intersect1188)
  Trim710: Trimmed (Trim709; Intersect1186)
  Trim711: Trimmed (Trim710; Intersect1187)
  Pocket242: profile Trim711, up to Plane788, deactivated
  Pad239: profile LineCorner60, up to Plane782, opposite side up to Plane783, deactivated
  Intersect1189: ToIntersect1 Plane786, ToIntersect2 Plane779
  Intersect1190: ToIntersect1 Plane779, ToIntersect2 Plane785
  Intersect1191: ToIntersect1 Plane789, ToIntersect2 Plane779
  Intersect1192: ToIntersect1 Plane790, ToIntersect2 Plane779
  Trim712: Trimmed (Intersect1192; Intersect1189)
  Trim713: Trimmed (Trim712; Intersect1191)
  Trim714: Trimmed (Trim713; Intersect1190)
  Pocket243: profile Trim714, up to Plane787, deactivated
  Intersect1193: ToIntersect1 Plane788, ToIntersect2 Plane781
  Intersect1194: ToIntersect1 Plane789, ToIntersect2 Plane781
  Intersect1195: ToIntersect1 Plane781, ToIntersect2 Plane787
  Intersect1196: ToIntersect1 Plane790, ToIntersect2 Plane781
  Trim715: Trimmed (Intersect1193; Intersect1196)
  Trim716: Trimmed (Trim715; Intersect1195)
  Trim717: Trimmed (Trim716; Intersect1194)
  Pad240: profile LineCorner60, up to Plane782, opposite side up to Plane783, deactivated
  Pocket244: profile Trim717, up to Plane786, deactivated
  Intersect1197: ToIntersect1 Plane787, ToIntersect2 Plane780
  Intersect1198: ToIntersect1 Plane789, ToIntersect2 Plane780
  Intersect1199: ToIntersect1 Plane788, ToIntersect2 Plane780
  Intersect1200: ToIntersect1 Plane790, ToIntersect2 Plane780
  Trim718: Trimmed (Intersect1197; Intersect1200)
  Trim719: Trimmed (Trim718; Intersect1199)
  Trim720: Trimmed (Trim719; Intersect1198)
  Pad241: profile LineCorner60, up to Plane782, opposite side up to Plane783
  Pocket245: profile Trim720, up to Plane785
